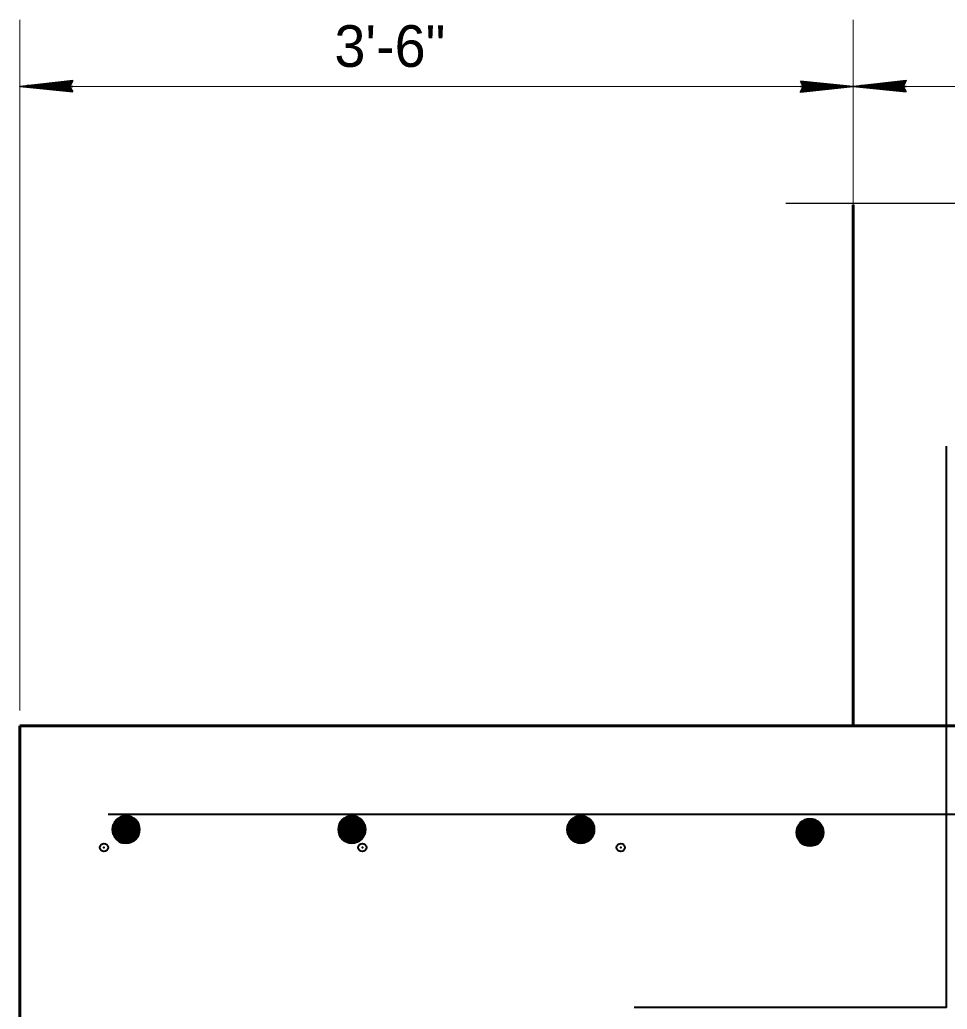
# Model space of a CAD drawing. Extents: x 14.14 to 17.34, y -1.61 to 0.38.
# Drawn here: x 15.9997 to 16.1851, y 0.0114 to 0.2092 of the extents above; entities that cross this region are included whole.
import ezdxf

# ---------------------------------------------------------------- set-up
doc = ezdxf.new("R2010")
doc.units = 0
doc.header["$LTSCALE"] = 0.0033
doc.header["$PDMODE"] = 32
doc.header["$PDSIZE"] = 0.00165
doc.layers.add('1', color=7, linetype='Continuous', lineweight=40)

msp = doc.modelspace()

# ---------------------------------------------------------------- linework, layer by layer
at = {"layer": '1', "lineweight": 13}
for p, q in [((15.999667, 0.071167), (15.999667, 0.20925)), ((16.166333, 0.17225), (16.166333, 0.20925)), ((16.000417, 0.195917), (16.499083, 0.195917))]:
    msp.add_line(p, q, dxfattribs=at)
at = {"layer": '1', "lineweight": 35}
for p, q in [((16.01025, 0.195917), (15.999667, 0.195917)), ((16.01, 0.195083), (16.002167, 0.196083)), ((16.01, 0.195083), (16.002167, 0.195917)), ((16.01, 0.197), (16.002667, 0.196167)), ((16.01, 0.196833), (16.002667, 0.196083)), ((16.01, 0.19675), (16.002667, 0.195917)), ((16.010083, 0.196583), (16.00275, 0.195833)), ((16.15575, 0.195917), (16.166333, 0.195917)), ((16.155917, 0.19525), (16.16325, 0.196)), ((16.156, 0.196917), (16.163833, 0.196)), ((16.156, 0.196917), (16.163833, 0.196)), ((16.156, 0.196833), (16.163833, 0.196)), ((16.156, 0.19675), (16.163833, 0.195917)), ((16.156, 0.19675), (16.163833, 0.19575)), ((16.156, 0.195083), (16.163333, 0.195917)), ((16.176917, 0.195917), (16.166333, 0.195917)), ((16.176667, 0.195083), (16.168833, 0.196083)), ((16.176667, 0.195083), (16.168833, 0.195917)), ((16.176667, 0.197), (16.169333, 0.196167)), ((16.176667, 0.196833), (16.169333, 0.196083)), ((16.176667, 0.19675), (16.169333, 0.195917)), ((16.17675, 0.196583), (16.169417, 0.195833)), ((16.01, 0.194917), (16.002167, 0.195833)), ((16.01, 0.194917), (16.002167, 0.195833)), ((16.01, 0.195), (16.002167, 0.195833)), ((16.156, 0.195), (16.163333, 0.19575)), ((16.156, 0.194833), (16.163333, 0.195667)), ((16.176667, 0.194917), (16.168833, 0.195833)), ((16.176667, 0.194917), (16.168833, 0.195833)), ((16.176667, 0.195), (16.168833, 0.195833))]:
    msp.add_line(p, q, dxfattribs=at)
at = {"layer": '1', "lineweight": 60}
for p, q in [((15.999667, -0.01525), (15.999667, 0.068083)), ((16.019083, 0.048917), (16.018917, 0.046)), ((16.019333, 0.048917), (16.019083, 0.046)), ((16.0195, 0.048917), (16.019333, 0.045917)), ((16.019667, 0.048917), (16.019417, 0.045917)), ((16.019833, 0.048917), (16.019667, 0.045917)), ((16.020083, 0.048917), (16.019917, 0.045917)), ((16.020333, 0.048917), (16.020083, 0.045917)), ((16.020417, 0.048833), (16.02025, 0.045917)), ((16.020583, 0.048833), (16.020417, 0.045917)), ((16.02075, 0.048833), (16.020583, 0.045917)), ((16.021, 0.048833), (16.02075, 0.045917)), ((16.021167, 0.048833), (16.021, 0.045917)), ((16.021417, 0.04875), (16.021167, 0.045833)), ((16.021667, 0.04875), (16.021417, 0.045833)), ((16.021833, 0.04875), (16.021667, 0.045833)), ((16.021917, 0.04875), (16.02175, 0.045833)), ((16.022083, 0.04875), (16.021917, 0.045833)), ((16.022167, 0.04875), (16.022, 0.045833)), ((16.022417, 0.048667), (16.022167, 0.04575)), ((16.022583, 0.048667), (16.022417, 0.04575)), ((16.02275, 0.048667), (16.0225, 0.04575)), ((16.022917, 0.048667), (16.02275, 0.04575)), ((16.023167, 0.048667), (16.023, 0.04575)), ((16.023417, 0.04675), (16.02325, 0.048583)), ((16.06425, 0.048917), (16.064083, 0.046)), ((16.0645, 0.048917), (16.06425, 0.046)), ((16.064667, 0.048917), (16.0645, 0.045917)), ((16.064833, 0.048917), (16.064583, 0.045917)), ((16.065, 0.048917), (16.064833, 0.045917)), ((16.06525, 0.048917), (16.065083, 0.045917)), ((16.0655, 0.048917), (16.06525, 0.045917)), ((16.065583, 0.048833), (16.065417, 0.045917)), ((16.06575, 0.048833), (16.065583, 0.045917)), ((16.065917, 0.048833), (16.06575, 0.045917)), ((16.066167, 0.048833), (16.065917, 0.045917)), ((16.066333, 0.048833), (16.066167, 0.045917)), ((16.066583, 0.04875), (16.066333, 0.045833)), ((16.066833, 0.04875), (16.066583, 0.045833)), ((16.067, 0.04875), (16.066833, 0.045833)), ((16.067083, 0.04875), (16.066917, 0.045833)), ((16.06725, 0.04875), (16.067083, 0.045833)), ((16.067333, 0.04875), (16.067167, 0.045833)), ((16.067583, 0.048667), (16.067333, 0.04575)), ((16.06775, 0.048667), (16.067583, 0.04575)), ((16.067917, 0.048667), (16.067667, 0.04575)), ((16.068083, 0.048667), (16.067917, 0.04575)), ((16.068333, 0.048667), (16.068167, 0.04575)), ((16.068583, 0.04675), (16.068417, 0.048583)), ((16.11, 0.048917), (16.109833, 0.046)), ((16.11025, 0.048917), (16.11, 0.046)), ((16.110417, 0.048917), (16.11025, 0.045917)), ((16.110583, 0.048917), (16.110333, 0.045917)), ((16.11075, 0.048917), (16.110583, 0.045917)), ((16.111, 0.048917), (16.110833, 0.045917)), ((16.11125, 0.048917), (16.111, 0.045917)), ((16.111333, 0.048833), (16.111167, 0.045917)), ((16.1115, 0.048833), (16.111333, 0.045917)), ((16.111667, 0.048833), (16.1115, 0.045917)), ((16.111917, 0.048833), (16.111667, 0.045917)), ((16.112083, 0.048833), (16.111917, 0.045917)), ((16.112333, 0.04875), (16.112083, 0.045833)), ((16.112583, 0.04875), (16.112333, 0.045833)), ((16.11275, 0.04875), (16.112583, 0.045833)), ((16.112833, 0.04875), (16.112667, 0.045833)), ((16.113, 0.04875), (16.112833, 0.045833)), ((16.113083, 0.04875), (16.112917, 0.045833)), ((16.113333, 0.048667), (16.113083, 0.04575)), ((16.1135, 0.048667), (16.113333, 0.04575)), ((16.113667, 0.048667), (16.113417, 0.04575)), ((16.113833, 0.048667), (16.113667, 0.04575)), ((16.114083, 0.048667), (16.113917, 0.04575)), ((16.114333, 0.04675), (16.114167, 0.048583)), ((16.155833, 0.048333), (16.155667, 0.045417)), ((16.156083, 0.048333), (16.155833, 0.045417)), ((16.15625, 0.048333), (16.156083, 0.045333)), ((16.156417, 0.048333), (16.156167, 0.045333)), ((16.156583, 0.048333), (16.156417, 0.045333)), ((16.156833, 0.048333), (16.156667, 0.045333)), ((16.157083, 0.048333), (16.156833, 0.045333)), ((16.157167, 0.04825), (16.157, 0.045333)), ((16.157333, 0.04825), (16.157167, 0.045333)), ((16.1575, 0.04825), (16.157333, 0.045333)), ((16.15775, 0.04825), (16.1575, 0.045333)), ((16.157917, 0.04825), (16.15775, 0.045333)), ((16.158167, 0.048167), (16.157917, 0.04525)), ((16.158417, 0.048167), (16.158167, 0.04525)), ((16.158583, 0.048167), (16.158417, 0.04525)), ((16.158667, 0.048167), (16.1585, 0.04525)), ((16.158833, 0.048167), (16.158667, 0.04525)), ((16.158917, 0.048167), (16.15875, 0.04525)), ((16.159167, 0.048083), (16.158917, 0.045167)), ((16.159333, 0.048083), (16.159167, 0.045167)), ((16.1595, 0.048083), (16.15925, 0.045167)), ((16.159667, 0.048083), (16.1595, 0.045167)), ((16.159917, 0.048083), (16.15975, 0.045167)), ((16.160167, 0.046167), (16.16, 0.048)), ((16.023417, 0.04675), (16.018667, 0.046)), ((16.068583, 0.04675), (16.063833, 0.046)), ((16.114333, 0.04675), (16.109583, 0.046)), ((16.160167, 0.046167), (16.155417, 0.045417))]:
    msp.add_line(p, q, dxfattribs=at)
at = {"layer": '1'}
for p, q in [((16.017333, 0.050417), (16.482, 0.050417)), ((16.02325, 0.048583), (16.022, 0.04975)), ((16.068417, 0.048583), (16.067167, 0.04975)), ((16.114167, 0.048583), (16.112917, 0.04975)), ((16.018833, 0.048917), (16.023417, 0.04675)), ((16.018917, 0.0475), (16.02275, 0.04675)), ((16.019, 0.047917), (16.022833, 0.04725)), ((16.019, 0.04775), (16.022833, 0.047)), ((16.019083, 0.0485), (16.023, 0.04775)), ((16.019083, 0.048333), (16.023, 0.047583)), ((16.019083, 0.048083), (16.022917, 0.047333)), ((16.019167, 0.048917), (16.023083, 0.04825)), ((16.019167, 0.04875), (16.023083, 0.048)), ((16.01925, 0.04925), (16.023083, 0.048583)), ((16.021167, 0.048417), (16.0225, 0.049417)), ((16.064, 0.048917), (16.068583, 0.04675)), ((16.064083, 0.0475), (16.067917, 0.04675)), ((16.064167, 0.047917), (16.068, 0.04725)), ((16.064167, 0.04775), (16.068, 0.047)), ((16.06425, 0.0485), (16.068167, 0.04775)), ((16.06425, 0.048333), (16.068167, 0.047583)), ((16.06425, 0.048083), (16.068083, 0.047333)), ((16.064333, 0.048917), (16.06825, 0.04825)), ((16.064333, 0.04875), (16.06825, 0.048)), ((16.064417, 0.04925), (16.06825, 0.048583)), ((16.066333, 0.048417), (16.067667, 0.049417)), ((16.10975, 0.048917), (16.114333, 0.04675)), ((16.109833, 0.0475), (16.113667, 0.04675)), ((16.109917, 0.047917), (16.11375, 0.04725)), ((16.109917, 0.04775), (16.11375, 0.047)), ((16.11, 0.0485), (16.113917, 0.04775)), ((16.11, 0.048333), (16.113917, 0.047583)), ((16.11, 0.048083), (16.113833, 0.047333)), ((16.110083, 0.048917), (16.114, 0.04825)), ((16.110083, 0.04875), (16.114, 0.048)), ((16.110167, 0.04925), (16.114, 0.048583)), ((16.112083, 0.048417), (16.113417, 0.049417)), ((16.155583, 0.048333), (16.160167, 0.046167)), ((16.155833, 0.047917), (16.15975, 0.047167)), ((16.155833, 0.04775), (16.15975, 0.047)), ((16.155833, 0.0475), (16.159667, 0.04675)), ((16.155917, 0.048333), (16.159833, 0.047667)), ((16.155917, 0.048167), (16.159833, 0.047417)), ((16.156, 0.048667), (16.159833, 0.048)), ((16.157917, 0.047833), (16.15925, 0.048833)), ((16.16, 0.048), (16.15875, 0.049167)), ((16.018667, 0.046167), (16.0225, 0.045417)), ((16.018667, 0.046), (16.0225, 0.04525)), ((16.01875, 0.046667), (16.022667, 0.045917)), ((16.01875, 0.0465), (16.022583, 0.04575)), ((16.01875, 0.04625), (16.022583, 0.045583)), ((16.018833, 0.047083), (16.02275, 0.046333)), ((16.018917, 0.047333), (16.02275, 0.046583)), ((16.023, 0.04575), (16.01925, 0.045333)), ((16.063833, 0.046167), (16.067667, 0.045417)), ((16.063833, 0.046), (16.067667, 0.04525)), ((16.063917, 0.046667), (16.067833, 0.045917)), ((16.063917, 0.0465), (16.06775, 0.04575)), ((16.063917, 0.04625), (16.06775, 0.045583)), ((16.064, 0.047083), (16.067917, 0.046333)), ((16.064083, 0.047333), (16.067917, 0.046583)), ((16.068167, 0.04575), (16.064417, 0.045333)), ((16.109583, 0.046167), (16.113417, 0.045417)), ((16.109583, 0.046), (16.113417, 0.04525)), ((16.109667, 0.046667), (16.113583, 0.045917)), ((16.109667, 0.0465), (16.1135, 0.04575)), ((16.109667, 0.04625), (16.1135, 0.045583)), ((16.10975, 0.047083), (16.113667, 0.046333)), ((16.109833, 0.047333), (16.113667, 0.046583)), ((16.113917, 0.04575), (16.110167, 0.045333)), ((16.155417, 0.045583), (16.15925, 0.044833)), ((16.1555, 0.046083), (16.159417, 0.045333)), ((16.1555, 0.045917), (16.159333, 0.045167)), ((16.1555, 0.045667), (16.159333, 0.045)), ((16.155583, 0.0465), (16.1595, 0.04575)), ((16.155667, 0.046917), (16.1595, 0.046167)), ((16.155667, 0.04675), (16.1595, 0.046)), ((16.15575, 0.047333), (16.159583, 0.046667)), ((16.15575, 0.047167), (16.159583, 0.046417)), ((16.155417, 0.045417), (16.15925, 0.044667)), ((16.15975, 0.045167), (16.156, 0.04475))]:
    msp.add_line(p, q, dxfattribs=at)
at = {"layer": '1', "lineweight": 35}
for points in [[(16.01025, 0.194833), (15.999667, 0.195917), (16.01025, 0.197083), (16.009667, 0.195917)], [(16.0095, 0.195833), (16.004833, 0.19575), (16.004833, 0.195833), (16.00575, 0.195833), (16.0095, 0.19575), (16.0065, 0.195667), (16.009667, 0.195583), (16.007417, 0.1955), (16.009667, 0.195417), (16.006167, 0.195667), (16.0015, 0.195833), (16.002417, 0.196083), (16.001167, 0.196083), (16.0095, 0.196083), (16.007083, 0.19625), (16.009667, 0.19625), (16.004333, 0.195833), (16.009667, 0.1965)], [(16.15575, 0.197), (16.166333, 0.195917), (16.15575, 0.19475), (16.156333, 0.195917)], [(16.1565, 0.196), (16.161167, 0.196083), (16.161167, 0.196), (16.16025, 0.196), (16.1565, 0.196083), (16.1595, 0.196167), (16.156333, 0.19625), (16.158583, 0.196333), (16.156333, 0.196417), (16.159833, 0.196167), (16.1645, 0.196), (16.163583, 0.19575), (16.164833, 0.19575), (16.1565, 0.19575), (16.158917, 0.195583), (16.156333, 0.195583), (16.161667, 0.196), (16.156333, 0.195333)], [(16.176917, 0.194833), (16.166333, 0.195917), (16.176917, 0.197083), (16.176333, 0.195917)], [(16.176167, 0.195833), (16.1715, 0.19575), (16.1715, 0.195833), (16.172417, 0.195833), (16.176167, 0.19575), (16.173167, 0.195667), (16.176333, 0.195583), (16.174083, 0.1955), (16.176333, 0.195417), (16.172833, 0.195667), (16.168167, 0.195833), (16.169083, 0.196083), (16.167833, 0.196083), (16.176167, 0.196083), (16.17375, 0.19625), (16.176333, 0.19625), (16.171, 0.195833), (16.176333, 0.1965)]]:
    msp.add_lwpolyline(points, close=True, dxfattribs=at)
for points in [[(16.0095, 0.195833), (16.009917, 0.195083), (16.009667, 0.195333), (16.0095, 0.195667), (16.00925, 0.195583), (16.009417, 0.19525), (16.009583, 0.196), (16.00975, 0.1965), (16.01, 0.196917)], [(16.1565, 0.196), (16.156083, 0.19675), (16.156333, 0.1965), (16.1565, 0.196167), (16.15675, 0.19625), (16.156583, 0.196583), (16.156417, 0.195833), (16.15625, 0.195333), (16.156, 0.194917)], [(16.176167, 0.195833), (16.176583, 0.195083), (16.176333, 0.195333), (16.176167, 0.195667), (16.175917, 0.195583), (16.176083, 0.19525), (16.17625, 0.196), (16.176417, 0.1965), (16.176667, 0.196917)]]:
    msp.add_lwpolyline(points, dxfattribs=at)
at = {"layer": '1', "lineweight": 25}
msp.add_lwpolyline([(16.152833, 0.172583), (16.236167, 0.172583), (16.242083, 0.166667), (16.253833, 0.178417), (16.25975, 0.1725), (16.343083, 0.1725)], dxfattribs=at)
at = {"layer": '1', "lineweight": 60}
for points in [[(15.999667, 0.068083), (16.166333, 0.068083), (16.166333, 0.17225)], [(16.166333, 0.068083), (16.228833, 0.068083), (16.228833, 0.088917), (16.2705, 0.088917), (16.2705, 0.068083), (16.333, 0.068083)], [(16.0225, 0.04525), (16.0225, 0.049417), (16.020833, 0.04475), (16.021333, 0.049917), (16.01925, 0.045333), (16.02, 0.049833), (16.021583, 0.044833), (16.018417, 0.048167), (16.02325, 0.048583), (16.02, 0.044917), (16.022, 0.04975), (16.018833, 0.048917), (16.018667, 0.046)], [(16.01925, 0.045333), (16.02075, 0.047583), (16.018583, 0.0485), (16.020583, 0.049917), (16.02075, 0.047667), (16.022417, 0.045333), (16.018417, 0.047667), (16.021167, 0.048417)], [(16.022, 0.04975), (16.02075, 0.047583), (16.023, 0.04575)], [(16.067667, 0.04525), (16.067667, 0.049417), (16.066, 0.04475), (16.0665, 0.049917), (16.064417, 0.045333), (16.065167, 0.049833), (16.06675, 0.044833), (16.063583, 0.048167), (16.068417, 0.048583), (16.065167, 0.044917), (16.067167, 0.04975), (16.064, 0.048917), (16.063833, 0.046)], [(16.064417, 0.045333), (16.065917, 0.047583), (16.06375, 0.0485), (16.06575, 0.049917), (16.065917, 0.047667), (16.067583, 0.045333), (16.063583, 0.047667), (16.066333, 0.048417)], [(16.067167, 0.04975), (16.065917, 0.047583), (16.068167, 0.04575)], [(16.113417, 0.04525), (16.113417, 0.049417), (16.11175, 0.04475), (16.11225, 0.049917), (16.110167, 0.045333), (16.110917, 0.049833), (16.1125, 0.044833), (16.109333, 0.048167), (16.114167, 0.048583), (16.110917, 0.044917), (16.112917, 0.04975), (16.10975, 0.048917), (16.109583, 0.046)], [(16.110167, 0.045333), (16.111667, 0.047583), (16.1095, 0.0485), (16.1115, 0.049917), (16.111667, 0.047667), (16.113333, 0.045333), (16.109333, 0.047667), (16.112083, 0.048417)], [(16.112917, 0.04975), (16.111667, 0.047583), (16.113917, 0.04575)], [(16.01825, 0.04725), (16.023417, 0.047917), (16.018833, 0.048917)], [(16.063417, 0.04725), (16.068583, 0.047917), (16.064, 0.048917)], [(16.109167, 0.04725), (16.114333, 0.047917), (16.10975, 0.048917)], [(16.155, 0.046667), (16.160167, 0.047333), (16.155583, 0.048333)], [(16.15925, 0.044667), (16.15925, 0.048833), (16.157583, 0.044167), (16.158083, 0.049333), (16.156, 0.04475), (16.15675, 0.04925), (16.158333, 0.04425), (16.155167, 0.047583), (16.16, 0.048), (16.15675, 0.044333), (16.15875, 0.049167), (16.155583, 0.048333), (16.155417, 0.045417)], [(16.156, 0.04475), (16.1575, 0.047), (16.155333, 0.047917), (16.157333, 0.049333), (16.1575, 0.047083), (16.159167, 0.04475), (16.155167, 0.047083), (16.157917, 0.047833)], [(16.15875, 0.049167), (16.1575, 0.047), (16.15975, 0.045167)]]:
    msp.add_lwpolyline(points, dxfattribs=at)
at = {"layer": '1'}
for points in [[(16.1225, 0.011833), (16.185, 0.011833), (16.185, 0.124)], [(16.018667, 0.046), (16.02075, 0.04475), (16.0225, 0.04525), (16.023417, 0.04675)], [(16.063833, 0.046), (16.065917, 0.04475), (16.067667, 0.04525), (16.068583, 0.04675)], [(16.109583, 0.046), (16.111667, 0.04475), (16.113417, 0.04525), (16.114333, 0.04675)], [(16.155417, 0.045417), (16.1575, 0.044167), (16.15925, 0.044667), (16.160167, 0.046167)]]:
    msp.add_lwpolyline(points, dxfattribs=at)
at = {"layer": '1', "lineweight": 60}
for centre in [(16.020917, 0.04735), (16.066083, 0.04735), (16.111833, 0.04735), (16.157667, 0.046767)]:
    msp.add_circle(centre, 0.00264, dxfattribs=at)
at = {"layer": '1'}
for p in [(16.020167, 0.045417), (16.066, 0.045417), (16.111917, 0.045417), (16.157833, 0.045417), (16.0165, 0.04375), (16.068167, 0.04375), (16.119833, 0.04375)]:
    msp.add_point(p, dxfattribs=at)

# ---------------------------------------------------------------- texts
msp.add_text('3\'-6"', height=0.008333, dxfattribs=at).set_placement((16.062583, 0.199833))

doc.saveas('drawing.dxf')
